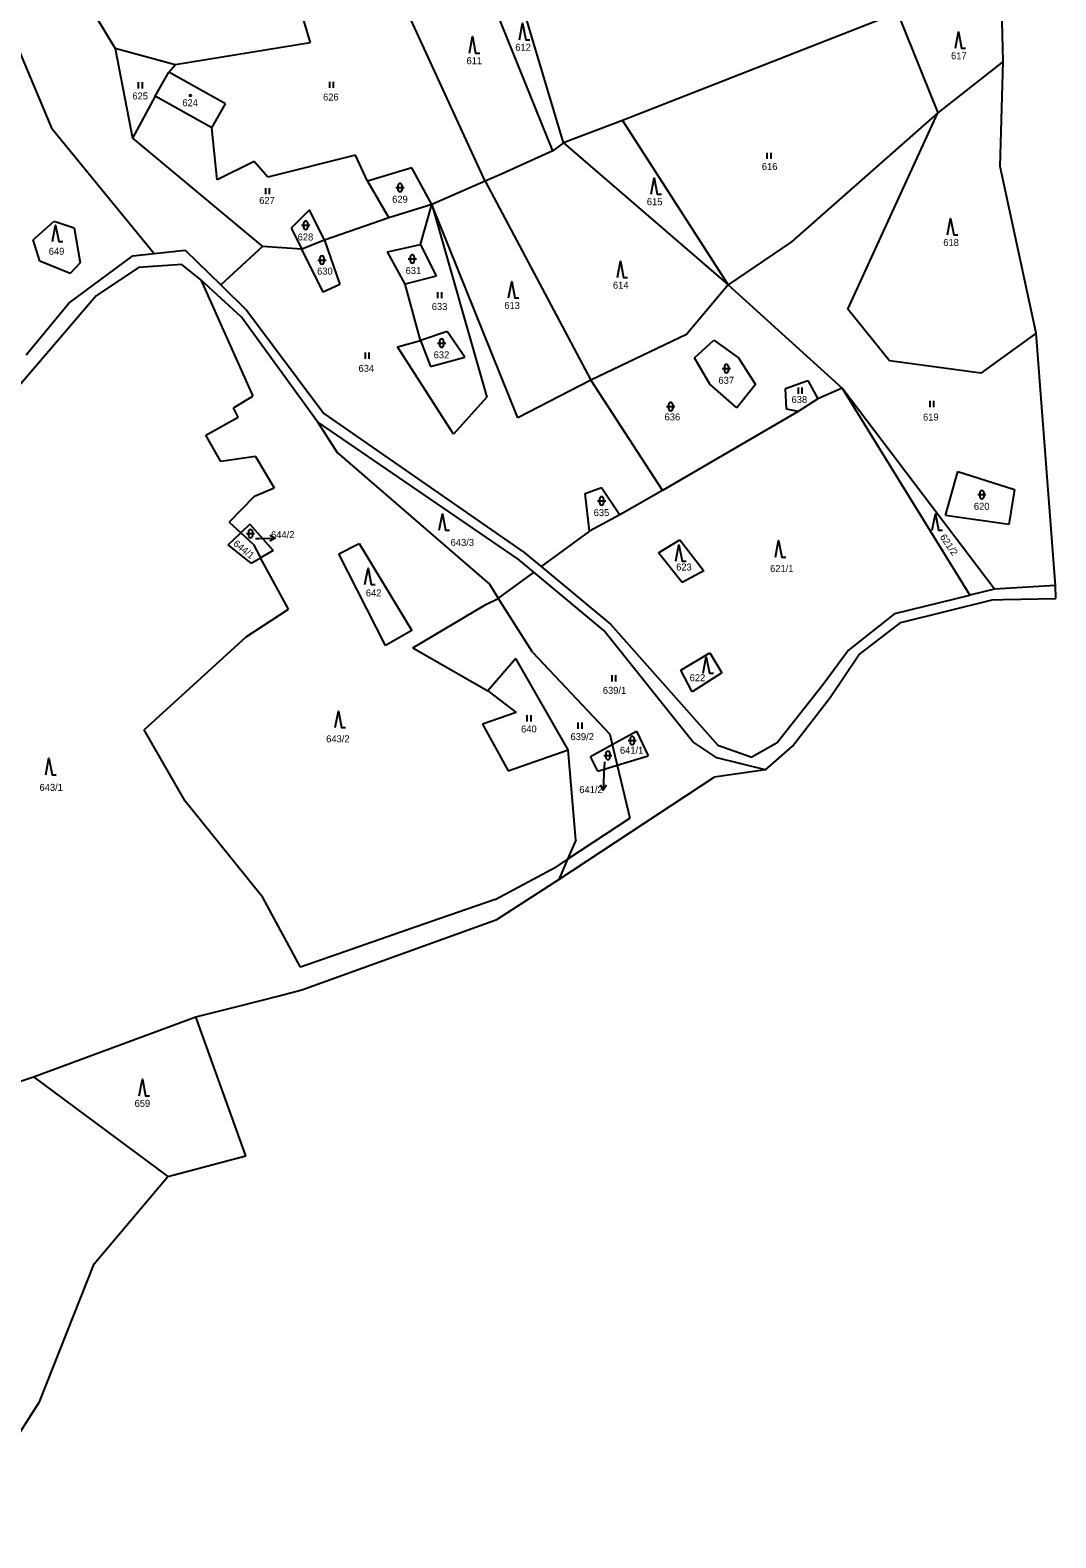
# Model space of a CAD drawing. Extents: x -670359 to -668019, y -978807 to -976674.
# Drawn here: x -668285.6 to -668036.1, y -977766.2 to -977399.4 of the extents above; entities that cross this region are included whole.
import ezdxf

# ---------------------------------------------------------------- set-up
doc = ezdxf.new("R2010")
doc.units = 0
for name, color, linetype in [('Hranice kat_území', 7, 'Continuous'), ('Hranice parcel', 7, 'Continuous'), ('Parcelní čísla', 7, 'Continuous'), ('Značky budov', 7, 'Continuous'), ('Značky kultur', 7, 'Continuous')]:
    doc.layers.add(name, color=color, linetype=linetype)

msp = doc.modelspace()

# ---------------------------------------------------------------- linework, layer by layer
at = {"layer": 'Hranice kat_území'}
for points in [[(-668048.93, -977407.09), (-668049.32, -977390.75)], [(-668049.59, -977432.6), (-668048.93, -977407.09)], [(-668040.85, -977473.16), (-668049.59, -977432.6)], [(-668036.13, -977534.55), (-668040.85, -977473.16)], [(-668036.08, -977537.68), (-668036.13, -977534.55)], [(-668073.77, -977543.55), (-668051.55, -977538.01)], [(-668051.55, -977538.01), (-668048.91, -977537.95)], [(-668048.91, -977537.95), (-668036.08, -977537.68)], [(-668083.98, -977551.44), (-668073.77, -977543.55)], [(-668090.99, -977561.76), (-668083.98, -977551.44)], [(-668100.14, -977573.6), (-668090.99, -977561.76)], [(-668106.67, -977579.37), (-668100.14, -977573.6)], [(-668157.02, -977606.09), (-668119.23, -977581.17)], [(-668106.67, -977579.37), (-668119.23, -977581.17)], [(-668172.1, -977615.81), (-668157.02, -977606.09)], [(-668219.48, -977632.95), (-668172.1, -977615.81)], [(-668225.04, -977634.36), (-668219.48, -977632.95)], [(-668234.92, -977636.86), (-668225.04, -977634.36)], [(-668245.26, -977639.48), (-668234.92, -977636.86)], [(-668233.16, -977673.28), (-668245.26, -977639.48)], [(-668252.07, -977678.3), (-668233.16, -977673.28)], [(-668270.04, -977699.59), (-668252.07, -977678.3)], [(-668283.32, -977733.14), (-668270.04, -977699.59)], [(-668304.59, -977766.25), (-668283.32, -977733.14)]]:
    msp.add_lwpolyline(points, dxfattribs=at)
at = {"layer": 'Hranice parcel'}
for points in [[(-668280.24, -977423.45), (-668302.7, -977370)], [(-668174.88, -977436.2), (-668201.75, -977377.71)], [(-668155.83, -977426.86), (-668170.44, -977377.93)], [(-668158.46, -977428.77), (-668177.76, -977381.04)], [(-668222.09, -977386.84), (-668217.44, -977402.53)], [(-668273.83, -977389.1), (-668264.93, -977403.94)], [(-668074.62, -977395.23), (-668141.46, -977421.45)], [(-668074.62, -977395.23), (-668064.75, -977419.58)], [(-668264.93, -977403.94), (-668260.7, -977425.74)], [(-668250.3, -977407.86), (-668264.93, -977403.94)], [(-668217.44, -977402.53), (-668250.3, -977407.86)], [(-668251.88, -977409.66), (-668250.3, -977407.86)], [(-668048.93, -977407.09), (-668064.75, -977419.58)], [(-668255.15, -977415.48), (-668251.88, -977409.66)], [(-668238.1, -977417.39), (-668251.88, -977409.66)], [(-668255.15, -977415.48), (-668260.7, -977425.74)], [(-668241.37, -977423.22), (-668255.15, -977415.48)], [(-668241.37, -977423.22), (-668238.1, -977417.39)], [(-668064.75, -977419.58), (-668100.38, -977450.98)], [(-668086.7, -977467.31), (-668064.75, -977419.58)], [(-668280.24, -977423.45), (-668255.4, -977453.78)], [(-668240.07, -977435.83), (-668241.37, -977423.22)], [(-668141.46, -977421.45), (-668155.83, -977426.86)], [(-668141.46, -977421.45), (-668115.8, -977461.41)], [(-668260.7, -977425.74), (-668229.03, -977452.08)], [(-668155.83, -977426.86), (-668158.46, -977428.77)], [(-668155.83, -977426.86), (-668115.8, -977461.41)], [(-668206.47, -977429.89), (-668227.8, -977435.22)], [(-668203.49, -977436.15), (-668206.47, -977429.89)], [(-668158.46, -977428.77), (-668170.75, -977434.42)], [(-668231.11, -977431.42), (-668240.07, -977435.83)], [(-668227.8, -977435.22), (-668231.11, -977431.42)], [(-668192.72, -977432.93), (-668203.49, -977436.15)], [(-668187.91, -977441.82), (-668192.72, -977432.93)], [(-668170.75, -977434.42), (-668174.88, -977436.2)], [(-668203.49, -977436.15), (-668198.36, -977445.14)], [(-668174.88, -977436.2), (-668187.91, -977441.82)], [(-668174.88, -977436.2), (-668149.21, -977484.56)], [(-668187.91, -977441.82), (-668198.36, -977445.14)], [(-668190.66, -977451.57), (-668187.91, -977441.82)], [(-668187.91, -977441.82), (-668174.51, -977488.71)], [(-668166.92, -977493.78), (-668187.91, -977441.82)], [(-668284.88, -977450.42), (-668279.75, -977445.88)], [(-668279.75, -977445.88), (-668274.85, -977447.57)], [(-668217.67, -977443.18), (-668222.07, -977447.58)], [(-668214, -977450.51), (-668217.67, -977443.18)], [(-668198.36, -977445.14), (-668214, -977450.51)], [(-668274.85, -977447.57), (-668273.46, -977456.02)], [(-668222.07, -977447.58), (-668219.53, -977452.72)], [(-668283.22, -977455.68), (-668284.88, -977450.42)], [(-668255.4, -977453.78), (-668247.85, -977452.95)], [(-668247.85, -977452.95), (-668239.22, -977461.44)], [(-668229.03, -977452.08), (-668239.22, -977461.44)], [(-668219.53, -977452.72), (-668229.03, -977452.08)], [(-668214, -977450.51), (-668219.53, -977452.72)], [(-668214.29, -977463.22), (-668219.53, -977452.72)], [(-668214, -977450.51), (-668210.22, -977461.29)], [(-668198.65, -977453.37), (-668190.66, -977451.57)], [(-668190.66, -977451.57), (-668186.84, -977459.31)], [(-668100.38, -977450.98), (-668115.8, -977461.41)], [(-668275.88, -977458.66), (-668283.22, -977455.68)], [(-668276.22, -977465.88), (-668260.65, -977454.35)], [(-668273.46, -977456.02), (-668275.88, -977458.66)], [(-668260.65, -977454.35), (-668255.4, -977453.78)], [(-668248.71, -977456.44), (-668259.26, -977457.16)], [(-668244.11, -977460.22), (-668248.71, -977456.44)], [(-668194.36, -977461.2), (-668198.65, -977453.37)], [(-668259.26, -977457.16), (-668269.51, -977464.09)], [(-668244.11, -977460.22), (-668231.46, -977488.47)], [(-668234.19, -977469.23), (-668244.11, -977460.22)], [(-668186.84, -977459.31), (-668194.36, -977461.2)], [(-668269.51, -977464.09), (-668296.09, -977495.03)], [(-668239.22, -977461.44), (-668232.92, -977467.64)], [(-668210.22, -977461.29), (-668214.29, -977463.22)], [(-668190.6, -977474.94), (-668194.36, -977461.2)], [(-668115.8, -977461.41), (-668125.92, -977473.45)], [(-668115.8, -977461.41), (-668088.02, -977486.55)], [(-668286.58, -977478.47), (-668276.22, -977465.88)], [(-668232.92, -977467.64), (-668214.17, -977492.67)], [(-668076.57, -977479.91), (-668086.7, -977467.31)], [(-668215.71, -977494.72), (-668234.19, -977469.23)], [(-668196.26, -977476.5), (-668190.6, -977474.94)], [(-668184.12, -977472.77), (-668190.6, -977474.94)], [(-668190.6, -977474.94), (-668188.18, -977481.27)], [(-668179.85, -977479), (-668184.12, -977472.77)], [(-668125.92, -977473.45), (-668149.21, -977484.56)], [(-668123.95, -977479.13), (-668119.24, -977474.89)], [(-668119.24, -977474.89), (-668113.3, -977479.18)], [(-668040.85, -977473.16), (-668054.33, -977482.93)], [(-668182.59, -977497.71), (-668196.26, -977476.5)], [(-668188.18, -977481.27), (-668179.85, -977479)], [(-668120.26, -977485.58), (-668123.95, -977479.13)], [(-668113.3, -977479.18), (-668109.13, -977485.65)], [(-668054.33, -977482.93), (-668076.57, -977479.91)], [(-668149.21, -977484.56), (-668166.92, -977493.78)], [(-668149.21, -977484.56), (-668131.74, -977511.42)], [(-668113.65, -977491.33), (-668120.26, -977485.58)], [(-668109.13, -977485.65), (-668113.65, -977491.33)], [(-668101.87, -977486.62), (-668096.44, -977484.65)], [(-668096.44, -977484.65), (-668093.95, -977489.14)], [(-668236.1, -977491.32), (-668231.46, -977488.47)], [(-668174.51, -977488.71), (-668182.59, -977497.71)], [(-668101.57, -977491.68), (-668101.87, -977486.62)], [(-668093.95, -977489.14), (-668098.79, -977492.25)], [(-668088.02, -977486.55), (-668093.95, -977489.14)], [(-668050.98, -977535.47), (-668088.02, -977486.55)], [(-668088.02, -977486.55), (-668057.01, -977536.93)], [(-668242.87, -977498), (-668234.95, -977493.61)], [(-668234.95, -977493.61), (-668236.1, -977491.32)], [(-668214.17, -977492.67), (-668165.43, -977526.51)], [(-668098.79, -977492.25), (-668131.74, -977511.42)], [(-668098.79, -977492.25), (-668101.57, -977491.68)], [(-668215.71, -977494.72), (-668210.9, -977502.18)], [(-668166.91, -977528.13), (-668215.71, -977494.72)], [(-668239.18, -977504.39), (-668242.87, -977498)], [(-668230.8, -977503.2), (-668239.18, -977504.39)], [(-668230.8, -977503.2), (-668226.24, -977510.79)], [(-668210.9, -977502.18), (-668173.89, -977534.19)], [(-668062.92, -977517.53), (-668059.9, -977506.83)], [(-668059.9, -977506.83), (-668046.12, -977511.23)], [(-668231.03, -977512.78), (-668226.24, -977510.79)], [(-668150.59, -977512.2), (-668146.61, -977510.74)], [(-668146.61, -977510.74), (-668142.12, -977517.38)], [(-668131.74, -977511.42), (-668142.12, -977517.38)], [(-668046.12, -977511.23), (-668047.54, -977519.75)], [(-668237.16, -977519.16), (-668231.03, -977512.78)], [(-668149.55, -977521.36), (-668150.59, -977512.2)], [(-668237.16, -977519.16), (-668234.35, -977521.74)], [(-668142.12, -977517.38), (-668149.55, -977521.36)], [(-668047.54, -977519.75), (-668062.92, -977517.53)], [(-668237.44, -977524.67), (-668234.35, -977521.74)], [(-668232.14, -977519.66), (-668234.35, -977521.74)], [(-668231.24, -977524.6), (-668234.35, -977521.74)], [(-668232.14, -977519.66), (-668226.44, -977526.02)], [(-668149.55, -977521.36), (-668161.26, -977529.96)], [(-668231.83, -977529.11), (-668237.44, -977524.67)], [(-668231.24, -977524.6), (-668229.52, -977527.79)], [(-668226.44, -977526.02), (-668229.52, -977527.79)], [(-668210.54, -977526.81), (-668205.55, -977524.32)], [(-668205.55, -977524.32), (-668192.78, -977545.46)], [(-668165.43, -977526.51), (-668161.26, -977529.96)], [(-668132.76, -977526.59), (-668127.52, -977523.42)], [(-668127.01, -977533.84), (-668132.76, -977526.59)], [(-668127.52, -977523.42), (-668121.7, -977530.98)], [(-668231.83, -977529.11), (-668229.52, -977527.79)], [(-668222.78, -977540.29), (-668229.52, -977527.79)], [(-668199.17, -977549.16), (-668210.54, -977526.81)], [(-668163.09, -977531.3), (-668166.91, -977528.13)], [(-668161.26, -977529.96), (-668144.4, -977543.94)], [(-668163.09, -977531.3), (-668171.72, -977537.64)], [(-668146.04, -977545.46), (-668163.09, -977531.3)], [(-668121.7, -977530.98), (-668127.01, -977533.84)], [(-668173.89, -977534.19), (-668171.72, -977537.64)], [(-668171.72, -977537.64), (-668171.91, -977537.78)], [(-668163.41, -977550.8), (-668171.72, -977537.64)], [(-668075.21, -977541.34), (-668057.01, -977536.93)], [(-668050.98, -977535.47), (-668057.01, -977536.93)], [(-668036.13, -977534.55), (-668050.98, -977535.47)], [(-668233.01, -977547.05), (-668222.78, -977540.29)], [(-668192.52, -977549.7), (-668174.77, -977539.2)], [(-668174.77, -977539.2), (-668171.91, -977537.78)], [(-668144.4, -977543.94), (-668118.32, -977573.41)], [(-668075.21, -977541.34), (-668086.5, -977550.31)], [(-668257.88, -977569.64), (-668233.01, -977547.05)], [(-668192.78, -977545.46), (-668199.17, -977549.16)], [(-668124.42, -977572.58), (-668146.04, -977545.46)], [(-668192.52, -977549.7), (-668174.23, -977560.19)], [(-668163.41, -977550.8), (-668144.6, -977570.7)], [(-668127.28, -977555.12), (-668120.24, -977550.96)], [(-668120.24, -977550.96), (-668117.37, -977555.79)], [(-668086.5, -977550.31), (-668092.72, -977558.65)], [(-668167.46, -977552.34), (-668174.23, -977560.19)], [(-668154.71, -977574.56), (-668167.46, -977552.34)], [(-668124.58, -977560.41), (-668127.28, -977555.12)], [(-668117.37, -977555.79), (-668124.58, -977560.41)], [(-668092.72, -977558.65), (-668103.87, -977572.83)], [(-668174.23, -977560.19), (-668167.36, -977565.47)], [(-668167.36, -977565.47), (-668175.55, -977568.31)], [(-668247.9, -977587.05), (-668257.88, -977569.64)], [(-668175.55, -977568.31), (-668169.31, -977579.65)], [(-668143.99, -977573.25), (-668138.13, -977570.02)], [(-668138.13, -977570.02), (-668135.22, -977575.97)], [(-668149.32, -977576.19), (-668143.99, -977573.25)], [(-668144.6, -977570.7), (-668143.99, -977573.25)], [(-668143.99, -977573.25), (-668142.8, -977578.26)], [(-668118.52, -977576.51), (-668124.42, -977572.58)], [(-668118.32, -977573.41), (-668110, -977576.29)], [(-668103.87, -977572.83), (-668110, -977576.29)], [(-668169.31, -977579.65), (-668154.71, -977574.56)], [(-668152.84, -977596.55), (-668154.71, -977574.56)], [(-668147.52, -977579.7), (-668149.32, -977576.19)], [(-668142.8, -977578.26), (-668135.22, -977575.97)], [(-668106.67, -977579.37), (-668118.52, -977576.51)], [(-668147.52, -977579.7), (-668142.8, -977578.26)], [(-668142.8, -977578.26), (-668139.74, -977591.17)], [(-668228.98, -977610.47), (-668247.9, -977587.05)], [(-668154.86, -977601.16), (-668139.74, -977591.17)], [(-668152.84, -977596.55), (-668154.86, -977601.16)], [(-668172.51, -977610.96), (-668157.62, -977602.98)], [(-668154.86, -977601.16), (-668157.62, -977602.98)], [(-668154.86, -977601.16), (-668157.02, -977606.09)], [(-668219.85, -977627.41), (-668228.98, -977610.47)], [(-668172.51, -977610.96), (-668185.89, -977615.6)], [(-668185.89, -977615.6), (-668195.69, -977618.96)], [(-668195.69, -977618.96), (-668207.27, -977623.01)], [(-668207.27, -977623.01), (-668219.85, -977627.41)], [(-668284.78, -977654.1), (-668245.26, -977639.48)], [(-668294.5, -977657.36), (-668284.78, -977654.1)], [(-668284.78, -977654.1), (-668252.07, -977678.3)]]:
    msp.add_lwpolyline(points, dxfattribs=at)
at = {"layer": 'Parcelní čísla'}
for p, q in [((-668227.31, -977522.29), (-668225.99, -977523)), ((-668230.75, -977523.13), (-668229.99, -977523.11)), ((-668145.88, -977577.47), (-668146, -977580.36)), ((-668145.36, -977583.09), (-668146.16, -977584.36))]:
    msp.add_line(p, q, dxfattribs=at)
for points in [[(-668229.99, -977523.11), (-668225.99, -977523), (-668227.27, -977523.79)], [(-668146, -977580.36), (-668146.16, -977584.36), (-668146.86, -977583.03)]]:
    msp.add_lwpolyline(points, dxfattribs=at)
at = {"layer": 'Značky budov'}
msp.add_circle((-668246.61, -977415.34), 0.175, dxfattribs=at)
at = {"layer": 'Značky kultur'}
for p, q in [((-668259.3, -977412.1), (-668259.3, -977413.6)), ((-668258.3, -977413.6), (-668258.3, -977412.1)), ((-668212.77, -977411.99), (-668212.77, -977413.49)), ((-668211.77, -977413.49), (-668211.77, -977411.99)), ((-668106.35, -977429.28), (-668106.35, -977430.78)), ((-668105.35, -977430.78), (-668105.35, -977429.28)), ((-668228.35, -977437.85), (-668228.35, -977439.35)), ((-668227.35, -977439.35), (-668227.35, -977437.85)), ((-668196.63, -977437.73), (-668194.63, -977437.73)), ((-668196.13, -977437.23), (-668196.13, -977438.23)), ((-668195.13, -977437.23), (-668195.13, -977438.23)), ((-668219.58, -977446.91), (-668217.58, -977446.91)), ((-668219.08, -977446.41), (-668219.08, -977447.41)), ((-668218.08, -977446.41), (-668218.08, -977447.41)), ((-668215.61, -977455.36), (-668213.61, -977455.36)), ((-668215.11, -977454.86), (-668215.11, -977455.86)), ((-668214.11, -977454.86), (-668214.11, -977455.86)), ((-668193.64, -977455.09), (-668191.64, -977455.09)), ((-668193.14, -977454.59), (-668193.14, -977455.59)), ((-668192.14, -977454.59), (-668192.14, -977455.59)), ((-668186.47, -977463.18), (-668186.47, -977464.68)), ((-668185.47, -977464.68), (-668185.47, -977463.18)), ((-668186, -977475.08), (-668186, -977476.08)), ((-668185, -977475.08), (-668185, -977476.08)), ((-668204.1, -977477.9), (-668204.1, -977479.4)), ((-668203.1, -977479.4), (-668203.1, -977477.9)), ((-668186.5, -977475.58), (-668184.5, -977475.58)), ((-668117.22, -977481.78), (-668115.22, -977481.78)), ((-668116.72, -977481.28), (-668116.72, -977482.28)), ((-668115.72, -977481.28), (-668115.72, -977482.28)), ((-668098.78, -977486.38), (-668098.78, -977487.88)), ((-668097.78, -977487.88), (-668097.78, -977486.38)), ((-668066.77, -977489.66), (-668066.77, -977491.16)), ((-668065.77, -977491.16), (-668065.77, -977489.66)), ((-668130.77, -977491.02), (-668128.77, -977491.02)), ((-668130.27, -977490.52), (-668130.27, -977491.52)), ((-668129.27, -977490.52), (-668129.27, -977491.52)), ((-668054.59, -977511.94), (-668054.59, -977512.94)), ((-668053.59, -977511.94), (-668053.59, -977512.94)), ((-668147.58, -977513.97), (-668145.58, -977513.97)), ((-668147.08, -977513.47), (-668147.08, -977514.47)), ((-668146.08, -977513.47), (-668146.08, -977514.47)), ((-668055.09, -977512.44), (-668053.09, -977512.44)), ((-668232.99, -977521.94), (-668230.99, -977521.94)), ((-668232.49, -977521.44), (-668232.49, -977522.44)), ((-668231.49, -977521.44), (-668231.49, -977522.44)), ((-668144.11, -977556.38), (-668144.11, -977557.88)), ((-668143.11, -977557.88), (-668143.11, -977556.38)), ((-668164.74, -977566.11), (-668164.74, -977567.61)), ((-668163.74, -977567.61), (-668163.74, -977566.11)), ((-668152.34, -977567.89), (-668152.34, -977569.39)), ((-668151.34, -977569.39), (-668151.34, -977567.89)), ((-668140.14, -977572.27), (-668138.14, -977572.27)), ((-668139.64, -977571.77), (-668139.64, -977572.77)), ((-668138.64, -977571.77), (-668138.64, -977572.77)), ((-668146.05, -977575.9), (-668144.05, -977575.9)), ((-668145.55, -977575.4), (-668145.55, -977576.4)), ((-668144.55, -977575.4), (-668144.55, -977576.4))]:
    msp.add_line(p, q, dxfattribs=at)
for points in [[(-668166.54, -977401.76), (-668165.79, -977397.76), (-668165.04, -977401.76), (-668164.04, -977401.76)], [(-668178.73, -977405.02), (-668177.98, -977401.02), (-668177.23, -977405.02), (-668176.23, -977405.02)], [(-668060.53, -977403.83), (-668059.78, -977399.83), (-668059.03, -977403.83), (-668058.03, -977403.83)], [(-668134.54, -977439.33), (-668133.79, -977435.33), (-668133.04, -977439.33), (-668132.04, -977439.33)], [(-668062.42, -977449.24), (-668061.67, -977445.24), (-668060.92, -977449.24), (-668059.92, -977449.24)], [(-668280.14, -977450.86), (-668279.39, -977446.86), (-668278.64, -977450.86), (-668277.64, -977450.86)], [(-668142.75, -977459.65), (-668142, -977455.65), (-668141.25, -977459.65), (-668140.25, -977459.65)], [(-668169.2, -977464.57), (-668168.45, -977460.57), (-668167.7, -977464.57), (-668166.7, -977464.57)], [(-668186.06, -977521.09), (-668185.31, -977517.09), (-668184.56, -977521.09), (-668183.56, -977521.09)], [(-668066.14, -977521.09), (-668065.39, -977517.09), (-668064.64, -977521.09), (-668063.64, -977521.09)], [(-668128.52, -977528.66), (-668127.77, -977524.66), (-668127.02, -977528.66), (-668126.02, -977528.66)], [(-668104.27, -977527.64), (-668103.52, -977523.64), (-668102.77, -977527.64), (-668101.77, -977527.64)], [(-668204.15, -977534.33), (-668203.4, -977530.33), (-668202.65, -977534.33), (-668201.65, -977534.33)], [(-668121.87, -977555.87), (-668121.12, -977551.87), (-668120.37, -977555.87), (-668119.37, -977555.87)], [(-668211.37, -977569.09), (-668210.62, -977565.09), (-668209.87, -977569.09), (-668208.87, -977569.09)], [(-668281.76, -977580.59), (-668281.01, -977576.59), (-668280.26, -977580.59), (-668279.26, -977580.59)], [(-668259.05, -977658.69), (-668258.3, -977654.69), (-668257.55, -977658.69), (-668256.55, -977658.69)]]:
    msp.add_lwpolyline(points, dxfattribs=at)
msp.add_circle((-668246.61, -977415.34), 0.175, dxfattribs=at)
for centre, start, end in [((-668195.63, -977437.23), 0, 180), ((-668195.63, -977438.23), 180, 0), ((-668218.58, -977446.41), 0, 180), ((-668218.58, -977447.41), 180, 0), ((-668214.61, -977454.86), 0, 180), ((-668214.61, -977455.86), 180, 0), ((-668192.64, -977454.59), 0, 180), ((-668192.64, -977455.59), 180, 0), ((-668185.5, -977475.08), 0, 180), ((-668185.5, -977476.08), 180, 0), ((-668116.22, -977481.28), 0, 180), ((-668116.22, -977482.28), 180, 0), ((-668129.77, -977490.52), 0, 180), ((-668129.77, -977491.52), 180, 0), ((-668054.09, -977511.94), 0, 180), ((-668146.58, -977513.47), 0, 180), ((-668146.58, -977514.47), 180, 0), ((-668054.09, -977512.94), 180, 0), ((-668231.99, -977521.44), 0, 180), ((-668231.99, -977522.44), 180, 0), ((-668139.14, -977571.77), 0, 180), ((-668139.14, -977572.77), 180, 0), ((-668145.05, -977575.4), 0, 180), ((-668145.05, -977576.4), 180, 0)]:
    msp.add_arc(centre, 0.5, start, end, dxfattribs=at)

# ---------------------------------------------------------------- texts
at = {"layer": 'Parcelní čísla'}
for s, height, p in [('612', 1.7, (-668167.58, -977404.46)), ('617', 1.7, (-668061.57, -977406.53)), ('611', 1.7, (-668179.44, -977407.72)), ('625', 1.7, (-668260.73, -977416.3)), ('624', 1.7, (-668248.57, -977417.94)), ('626', 1.7, (-668214.34, -977416.56)), ('616', 1.7, (-668107.6, -977433.48)), ('627', 1.7, (-668229.87, -977441.72)), ('629', 1.7, (-668197.52, -977441.43)), ('615', 1.7, (-668135.58, -977442.03)), ('628', 1.7, (-668220.51, -977450.61)), ('649', 1.7, (-668281.07, -977454.09)), ('618', 1.7, (-668063.46, -977451.94)), ('630', 1.7, (-668215.79, -977458.92)), ('631', 1.7, (-668194.25, -977458.79)), ('614', 1.7, (-668143.82, -977462.35)), ('633', 1.7, (-668187.9, -977467.53)), ('613', 1.7, (-668170.24, -977467.27)), ('632', 1.7, (-668187.43, -977479.28)), ('634', 1.7, (-668205.71, -977482.57)), ('637', 1.7, (-668118.15, -977485.48)), ('638', 1.7, (-668100.37, -977490.17)), ('636', 1.7, (-668131.26, -977494.39)), ('619', 1.7, (-668068.38, -977494.42)), ('620', 1.7, (-668056.02, -977516.14)), ('635', 1.7, (-668148.51, -977517.67)), ('644/2', 1.7, (-668226.99, -977523.03)), ('644/2', 0.1, (-668230.75, -977523.13)), ('643/3', 1.7, (-668183.31, -977524.92)), ('623', 1.7, (-668128.44, -977530.91)), ('621/1', 1.7, (-668105.59, -977531.26)), ('642', 1.7, (-668203.94, -977537.21)), ('639/1', 1.7, (-668146.28, -977560.91)), ('622', 1.7, (-668125.16, -977557.84)), ('640', 1.7, (-668166.17, -977570.31)), ('639/2', 1.7, (-668154.14, -977572.17)), ('643/2', 1.7, (-668213.58, -977572.7)), ('641/1', 1.7, (-668142.12, -977575.49)), ('641/2', 0.1, (-668145.88, -977577.47)), ('643/1', 1.7, (-668283.31, -977584.51)), ('641/2', 1.7, (-668152.01, -977585.06)), ('659', 1.7, (-668260.19, -977661.39))]:
    msp.add_text(s, height=height, dxfattribs=at).set_placement(p)
for s, rotation, p in [('621/2', 304.2157, (-668064.38, -977522.76)), ('644/1', 321.3235, (-668236.35, -977524.66))]:
    msp.add_text(s, height=1.7, rotation=rotation, dxfattribs=at).set_placement(p)

doc.saveas('drawing.dxf')
